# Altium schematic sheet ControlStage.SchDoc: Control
size A3; Date: Not shown in title block; ApprovedBy: Not shown in title block; CheckedBy: Not shown in title block; Author: Not shown in title block; CompanyName: Not shown in title block; DrawnBy: Hely Zhang; Engineer: Hely Zhang; Organization: Not shown in title block; Address1: Not shown in title block; Address2: Not shown in title block; Address3: Not shown in title block; Address4: Not shown in title block; DocumentNumber: 5; Revision: Use project parameter SCH_Rev; SheetNumber: 5; SheetTotal: 6; PageSetup: Record=PageOptions¦CenterHorizontal=True¦CenterVertical=True¦PrintScale=1.00¦XCorrection=1.00¦YCorrection=1.00¦PrintKind=0¦BorderSize=5000000¦LeftOffset=0¦BottomOffset=0¦Orientation=2¦PaperLength=1000¦PaperWidth=1000¦Scale=100¦PaperSource=15¦PrintQuality=600¦MediaType=1¦DitherType=10¦PaperKind=Letter¦PrintScaleMode=1
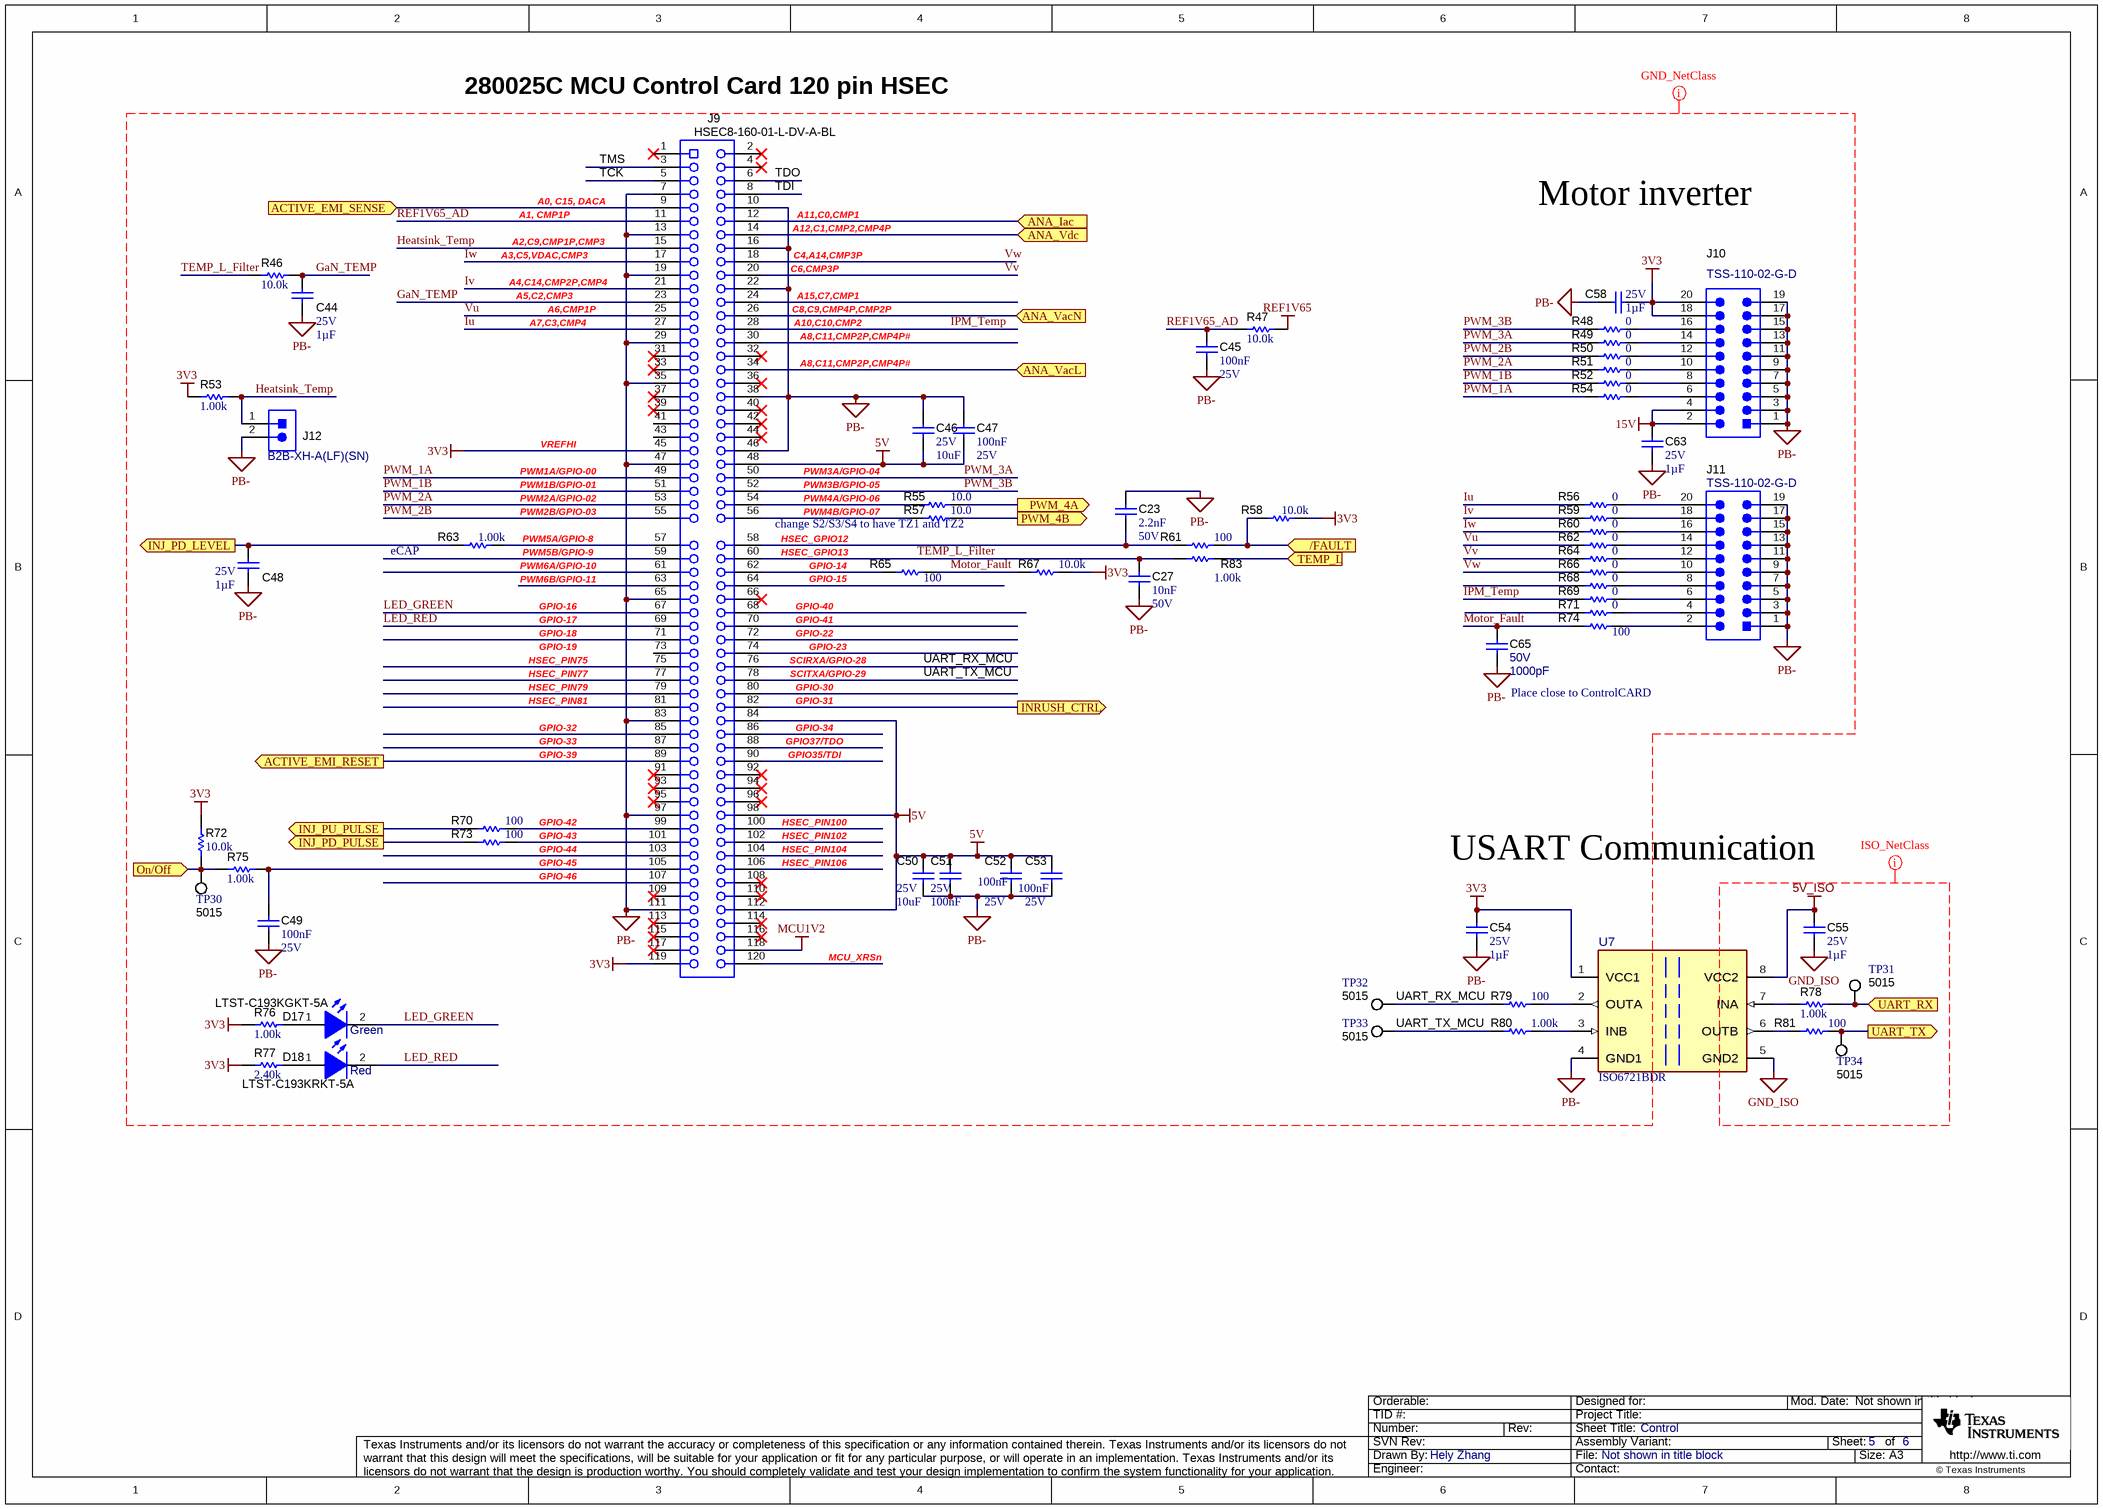
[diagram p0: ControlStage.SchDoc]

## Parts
C23  Cap_F: 2.2nF  VDC_V: 50V  [0603]  (hidden comment: GRM188R71H222KA01D)
C27  Cap_F: 10nF  VDC_V: 50V  [0603]  (hidden comment: GRM188R71H103KA01D)
C44  VDC_V: 25V  Cap_F: 1µF  [0603]  (hidden comment: GRJ188R71E105KE11D)
C45  Cap_F: 100nF  VDC_V: 25V  [0603]  (hidden comment: GRM188R71E104KA01D)
C46  VDC_V: 25V  ValueDisplayed: 10uF  [1206_180]  (hidden comment: GRM31CR71E106KA12L)
C47  Cap_F: 100nF  VDC_V: 25V  [0603]  (hidden comment: GRM188R71E104KA01D)
C48  VDC_V: 25V  Cap_F: 1µF  [0603]  (hidden comment: GRJ188R71E105KE11D)
C49  Cap_F: 100nF  VDC_V: 25V  [0603]  (hidden comment: GRM188R71E104KA01D)
C50  VDC_V: 25V  ValueDisplayed: 10uF  [1206_180]  (hidden comment: GRM31CR71E106KA12L)
C51  Cap_F: 100nF  VDC_V: 25V  [0603]  (hidden comment: GRM188R71E104KA01D)
C52  Cap_F: 100nF  VDC_V: 25V  [0603]  (hidden comment: GRM188R71E104KA01D)
C53  Cap_F: 100nF  VDC_V: 25V  [0603]  (hidden comment: GRM188R71E104KA01D)
C54  VDC_V: 25V  Cap_F: 1µF  [0603]  (hidden comment: GRJ188R71E105KE11D)
C55  VDC_V: 25V  Cap_F: 1µF  [0603]  (hidden comment: GRJ188R71E105KE11D)
C58  VDC_V: 25V  Cap_F: 1µF  [0603]  (hidden comment: GRJ188R71E105KE11D)
C63  VDC_V: 25V  Cap_F: 1µF  [0603]  (hidden comment: GRJ188R71E105KE11D)
C65  VDC_V: 50V  ValueDisplayed: 1000pF  [0603]  (hidden comment: GCJ188R71H102KA01D)
D17  LTST-C193KGKT-5A  value Green  [LTST-C193_Green]
D18  LTST-C193KRKT-5A  value Red  [LTST-C193_Red]
J9  HSEC8-160-01-L-DV-A-BL  [controlCARD-120HSEC]
J10  TSS-110-02-G-D  [Samtec_TSS-110-02-G-D]
J11  TSS-110-02-G-D  [Samtec_TSS-110-02-G-D]
J12  B2B-XH-A(LF)(SN)  [JST_B2B-XH-A]
R46  ValueDisplayed: 10.0k  [0603]  (hidden comment: RC0603FR-0710KL)
R47  ValueDisplayed: 10.0k  [0603]  (hidden comment: RC0603FR-0710KL)
R48  ValueDisplayed: 0  [0603]  (hidden comment: RC0603JR-070RL)
R49  ValueDisplayed: 0  [0603]  (hidden comment: RC0603JR-070RL)
R50  ValueDisplayed: 0  [0603]  (hidden comment: RC0603JR-070RL)
R51  ValueDisplayed: 0  [0603]  (hidden comment: RC0603JR-070RL)
R52  ValueDisplayed: 0  [0603]  (hidden comment: RC0603JR-070RL)
R53  ValueDisplayed: 1.00k  [0603]  (hidden comment: RC0603FR-071KL)
R54  ValueDisplayed: 0  [0603]  (hidden comment: RC0603JR-070RL)
R55  ValueDisplayed: 10.0  [0603]  (hidden comment: RC0603FR-0710RL)
R56  ValueDisplayed: 0  [0603]  (hidden comment: RC0603JR-070RL)
R57  ValueDisplayed: 10.0  [0603]  (hidden comment: RC0603FR-0710RL)
R58  ValueDisplayed: 10.0k  [0603]  (hidden comment: RC0603FR-0710KL)
R59  ValueDisplayed: 0  [0603]  (hidden comment: RC0603JR-070RL)
R60  ValueDisplayed: 0  [0603]  (hidden comment: RC0603JR-070RL)
R61  ValueDisplayed: 100  [0603]  (hidden comment: RC0603FR-07100RL)
R62  ValueDisplayed: 0  [0603]  (hidden comment: RC0603JR-070RL)
R63  ValueDisplayed: 1.00k  [0603]  (hidden comment: RC0603FR-071KL)
R64  ValueDisplayed: 0  [0603]  (hidden comment: RC0603JR-070RL)
R65  ValueDisplayed: 100  [0603]  (hidden comment: RC0603FR-07100RL)
R66  ValueDisplayed: 0  [0603]  (hidden comment: RC0603JR-070RL)
R67  ValueDisplayed: 10.0k  [0603]  (hidden comment: RC0603FR-0710KL)
R68  ValueDisplayed: 0  [0603]  (hidden comment: RC0603JR-070RL)
R69  ValueDisplayed: 0  [0603]  (hidden comment: RC0603JR-070RL)
R70  ValueDisplayed: 100  [0603]  (hidden comment: RC0603FR-07100RL)
R71  ValueDisplayed: 0  [0603]  (hidden comment: RC0603JR-070RL)
R72  ValueDisplayed: 10.0k  [0603]  (hidden comment: RC0603FR-0710KL)
R73  ValueDisplayed: 100  [0603]  (hidden comment: RC0603FR-07100RL)
R74  ValueDisplayed: 100  [0603]  (hidden comment: RC0603FR-07100RL)
R75  ValueDisplayed: 1.00k  [0603]  (hidden comment: RC0603FR-071KL)
R76  ValueDisplayed: 1.00k  [0603]  (hidden comment: RC0603FR-071KL)
R77  ValueDisplayed: 2.40k  [0603]  (hidden comment: RC0603FR-072K4L)
R78  ValueDisplayed: 1.00k  [0603]  (hidden comment: RC0603FR-071KL)
R79  ValueDisplayed: 100  [0603]  (hidden comment: RC0603FR-07100RL)
R80  ValueDisplayed: 1.00k  [0603]  (hidden comment: RC0603FR-071KL)
R81  ValueDisplayed: 100  [0603]  (hidden comment: RC0603FR-07100RL)
R83  ValueDisplayed: 1.00k  [0603]  (hidden comment: RC0603FR-071KL)
TP30  5015  [Testpoint_Keystone_Miniature]
TP31  5015  [Testpoint_Keystone_Miniature]
TP32  5015  [Testpoint_Keystone_Miniature]
TP33  5015  [Testpoint_Keystone_Miniature]
TP34  5015  [Testpoint_Keystone_Miniature]
U7  ISO6721BDR  [D0008A-MFG]

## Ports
/FAULT (in), ACTIVE_EMI_RESET (out), ACTIVE_EMI_SENSE (in), ANA_Iac (in), ANA_VacL (in), ANA_VacN (in), ANA_Vdc (in), INJ_PD_LEVEL (out), INJ_PD_PULSE (out), INJ_PU_PULSE (out), INRUSH_CTRL (out), On/Off (in), PWM_4A (out), PWM_4B (out), TEMP_L (in), UART_RX (in), UART_TX (out)

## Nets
3V3: C54.1 C58.1 J9.45 J9.119 J10.18 J10.20 R53.2 R58.2 R67.2 R72.2 R76.2 R77.2 U7.1(VCC1)
5V: C46.2 C47.2 C50.1 C51.1 C52.1 C53.1 J9.48 J9.84 J9.98 J9.112
5V_ISO: C55.1 U7.8(VCC2)
15V: C63.1 J10.2 J10.4
GND_ISO: C55.2 U7.5(GND2)
MCU1V2: J9.118
PB-: C23.1 C27.2 C44.2 C45.2 C46.1 C47.1 C48.2 C49.2 C50.2 C51.2 C52.2 C53.2 C54.2 C58.2 C63.2 C65.1 J9.7 J9.10 J9.13 J9.16 J9.19 J9.22 J9.29 J9.35 J9.38 J9.46 J9.47 J9.65 J9.83 J9.97 J9.111 J10.1 J10.3 J10.5 J10.7 J10.9 J10.11 J10.13 J10.15 J10.17 J10.19 J11.1 J11.3 J11.5 J11.7 J11.9 J11.11 J11.13 J11.15 J11.17 J11.19 J12.2 U7.4(GND1)
REF1V65: R47.2
/FAULT: R58.1 R61.2 ; port /FAULT
ACTIVE_EMI_RESET: J9.89 ; port ACTIVE_EMI_RESET
ACTIVE_EMI_SENSE: J9.9 ; port ACTIVE_EMI_SENSE
ANA_Iac: J9.12 ; port ANA_Iac
ANA_VacL: J9.34 ; port ANA_VacL
ANA_VacN: J9.26 ; port ANA_VacN
ANA_Vdc: J9.14 ; port ANA_Vdc
GaN_TEMP: C44.1 J9.23 R46.2
Heatsink_Temp: J9.15 J12.1 R53.1
INJ_PD_LEVEL: C48.1 R63.2 ; port INJ_PD_LEVEL
INJ_PD_PULSE: R73.1 ; port INJ_PD_PULSE
INJ_PU_PULSE: R70.1 ; port INJ_PU_PULSE
INRUSH_CTRL: J9.82 ; port INRUSH_CTRL
IPM_Temp: J9.28 R69.1
Iu: J9.27 R56.1
Iv: J9.21 R59.1
Iw: J9.17 R60.1
LED_GREEN: D17.2(K) J9.67
LED_RED: D18.2(K) J9.69
Motor_Fault: C65.2 R65.2 R67.1 R74.1
On/Off: R72.1 R75.2 TP30.1 ; port On/Off
PWM_1A: J9.49 R54.1
PWM_1B: J9.51 R52.1
PWM_2A: J9.53 R51.1
PWM_2B: J9.55 R50.1
PWM_3A: J9.50 R49.1
PWM_3B: J9.52 R48.1
PWM_4A: R55.2 ; port PWM_4A
PWM_4B: R57.2 ; port PWM_4B
REF1V65_AD: C45.1 J9.11 R47.1
TCK: J9.5
TDI: J9.8
TDO: J9.6
TEMP_L: R83.1 ; port TEMP_L
TEMP_L_Filter: C27.1 J9.60 R46.1 R83.2
TMS: J9.3
UART_RX: R78.1 TP31.1 ; port UART_RX
UART_RX_MCU: J9.76 R79.1 TP32.1
UART_TX: R81.2 TP34.1 ; port UART_TX
UART_TX_MCU: J9.78 R80.2 TP33.1
Vu: J9.25 R62.1
Vv: J9.20 R64.1
Vw: J9.18 R66.1
NetC23_2: C23.2 J9.58 R61.1
NetC49_1: C49.1 J9.105 R75.1
NetD17_1: D17.1(A) R76.1
NetD18_1: D18.1(A) R77.1
NetJ9_54: J9.54 R55.1
NetJ9_56: J9.56 R57.1
NetJ9_57: J9.57 R63.1
NetJ9_62: J9.62 R65.1
NetJ9_99: J9.99 R70.2
NetJ9_101: J9.101 R73.2
NetJ10_6: J10.6 R54.2
NetJ10_8: J10.8 R52.2
NetJ10_10: J10.10 R51.2
NetJ10_12: J10.12 R50.2
NetJ10_14: J10.14 R49.2
NetJ10_16: J10.16 R48.2
NetJ11_2: J11.2 R74.2
NetJ11_4: J11.4 R71.2
NetJ11_6: J11.6 R69.2
NetJ11_8: J11.8 R68.2
NetJ11_10: J11.10 R66.2
NetJ11_12: J11.12 R64.2
NetJ11_14: J11.14 R62.2
NetJ11_16: J11.16 R60.2
NetJ11_18: J11.18 R59.2
NetJ11_20: J11.20 R56.2
NetR78_2: R78.2 U7.7(INA)
NetR79_2: R79.2 U7.2(OUTA)
NetR80_1: R80.1 U7.3(INB)
NetR81_1: R81.1 U7.6(OUTB)

Not connected (* = marked no-connect by the designer): J9 1* 2* 4* 24 30 31* 32* 33* 36* 37* 39* 40* 41 42* 43 44* 59 61 63 64 66* 68 70 71 72 73 74 75 77 79 80 81 85 86 87 88 90 91* 92* 93* 94* 95* 96* 100 102 103 104 106 107 108* 109* 110* 113* 114* 115* 116* 117* 120; R68 1; R71 1

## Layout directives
net class GND_NetClass: 3V3, 5V, 5V_ISO, 15V, GaN_TEMP, GND_ISO, Heatsink_Temp, IPM_Temp, Iu, Iv, Iw, LED_GREEN, LED_RED, MCU1V2, Motor_Fault, PB-, PWM_1A, PWM_1B, PWM_2A, PWM_2B, PWM_3A, PWM_3B, REF1V65, REF1V65_AD, TCK, TDI, TDO, TEMP_L_Filter, TMS, UART_RX_MCU, UART_TX_MCU, Vu, Vv, Vw
net class ISO_NetClass: 5V_ISO, GND_ISO

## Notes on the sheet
- 280025C MCU Control Card 120 pin HSEC
- A1, CMP1P
- A3,C5,VDAC,CMP3
- A2,C9,CMP1P,CMP3
- A0, C15, DACA
- A11,C0,CMP1
- C4,A14,CMP3P
- A12,C1,CMP2,CMP4P
- Motor inverter
- A5,C2,CMP3
- A4,C14,CMP2P,CMP4
- A7,C3,CMP4
- A6,CMP1P
- C6,CMP3P
- A15,C7,CMP1
- A10,C10,CMP2
- C8,C9,CMP4P,CMP2P
- A8,C11,CMP2P,CMP4P#
- VREFHI
- PWM1A/GPIO-00
- PWM1B/GPIO-01
- PWM2A/GPIO-02
- (near R63) PWM2B/GPIO-03
- PWM3A/GPIO-04
- PWM3B/GPIO-05
- PWM4A/GPIO-06
- PWM4B/GPIO-07
- (near R63) eCAP
- (near R63) PWM5A/GPIO-8
- (near R63) PWM5B/GPIO-9
- (near R63) PWM6A/GPIO-10
- (near R63) PWM6B/GPIO-11
- (near R57) change S2/S3/S4 to have TZ1 and TZ2
- HSEC_GPIO12
- HSEC_GPIO13
- GPIO-14
- GPIO-15
- GPIO-16
- GPIO-17
- GPIO-18
- GPIO-19
- HSEC_PIN75
- GPIO-40
- GPIO-41
- GPIO-22
- GPIO-23
- SCIRXA/GPIO-28
- HSEC_PIN77
- HSEC_PIN79
- HSEC_PIN81
- GPIO-32
- GPIO-30
- GPIO-31
- GPIO-34
- SCITXA/GPIO-29
- (near C65) Place close to ControlCARD
- GPIO-33
- GPIO-39
- GPIO37/TDO
- GPIO35/TDI
- GPIO-42
- GPIO-43
- GPIO-44
- GPIO-45
- HSEC_PIN100
- HSEC_PIN102
- HSEC_PIN104
- HSEC_PIN106
- GPIO-46
- USART Communication
- MCU_XRSn

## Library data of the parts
C23 = CMP-0007443-4: CAP, CERM, 2200 pF, 50 V, +/- 10%, X7R, 0603; Manufacturer: MuRata; TaMin_C: -55°C; Polarized: N; SizeAreaWB_mm2: 4.68; Value1: Unknown; U/M: EA; Value: 2200pF; TaMax_C: 125°C; SizeZ_mm: 1; SizeX_mm: 1.6; SizeY_mm: 0.8; SizeArea_mm2: 1.28; AEC Category: Q200
C27 = CMP-0007433-4: CAP, CERM, 0.01 uF, 50 V, +/- 10%, X7R, 0603; Manufacturer: MuRata; TaMin_C: -55°C; Polarized: N; SizeAreaWB_mm2: 4.68; Value1: Unknown; U/M: EA; Value: 0.01uF; TaMax_C: 125°C; SizeZ_mm: 1; SizeX_mm: 1.6; SizeY_mm: 0.8; SizeArea_mm2: 1.28; AEC Category: Q200
C44 C48 C54 C55 C58 C63 = CMP-0079720-2: CAP, CERM, 1 µF, 25 V,+/- 10%, X7R, 0603; Manufacturer: MuRata; AEC Category: Q200; TaMin_C: -55°C; AEC Qualified: N; SizeAreaWB_mm2: 4.68; SizeArea_mm2: 1.28; Value: 1uF; SizeZ_mm: 1; SizeX_mm: 1.6; U/M: EA; MFG_Status: TI_Obsolete; SizeY_mm: 0.8; TaMax_C: 125°C
C45 C47 C49 C51-C53 = CMP-0007404-5: CAP, CERM, 0.1 uF, 25 V, +/- 10%, X7R, 0603; Manufacturer: MuRata; ValueDisplayed: 0.1uF; SizeAreaWB_mm2: 4.68; MFG_Status: TI_Obsolete; SizeZ_mm: 1; SizeY_mm: 0.8; Value: 0.1uF; AEC Category: Q200; Value1: Unknown; SizeX_mm: 1.6; TaMin_C: -55°C; Polarized: N; TaMax_C: 125°C; SizeArea_mm2: 1.28; U/M: EA
C46 C50 = CMP-0008965-2: CAP, CERM, 10 uF, 25 V, +/- 10%, X7R, 1206; Manufacturer: MuRata; TaMin_C: -55°C; Polarized: N; SizeAreaWB_mm2: 10.92; Value1: Unknown; U/M: EA; Value: 10uF; TaMax_C: 125°C; SizeZ_mm: 1.8; SizeX_mm: 3.2; SizeY_mm: 1.6; Cap_Case: 2220; SizeArea_mm2: 5.12; Cap_F: 10µF; AEC Category: Q200
C65 = CMP-0007432-5: CAP, CERM, 1000 pF, 50 V, +/- 10%, X7R, 0603; Manufacturer: MuRata; TaMin_C: -55°C; Polarized: N; SizeAreaWB_mm2: 4.68; Value1: Unknown; U/M: EA; Value: 1000pF; TaMax_C: 125°C; SizeZ_mm: 1; SizeX_mm: 1.6; SizeY_mm: 0.8; SizeArea_mm2: 1.28; Cap_F: 1nF; AEC Category: Q200
D17 = CMP-0079921-3: LED, Green, SMD; Manufacturer: Lite-On; Tjmax_C: 85°C; Value2: 2V; SizeY_mm: 0.8; Io_A: 5mA; SizeAreaWB_mm2: 4.68; Type: AlInGaP; SizeX_mm: 1.6; SizeZ_mm: 0.45; SizeArea_mm2: 1.28; Value1: W
D18 = CMP-0079922-3: LED, Red, SMD; Manufacturer: Lite-On; SizeX_mm: 1.6; Value2: 2V; SizeY_mm: 0.8; Green_REACh: Incomplete; SizeAreaWB_mm2: 4.68; Green_Lifecycle: Not Set; Value1: W; Io_A: 5mA; Type: AlInGaP; SizeZ_mm: 0.45; Tjmax_C: 85°C; SizeArea_mm2: 1.28
J9 = controlCARD-120HSEC: C2000 controlCARD-120HSEC connector, SMT; Manufacturer: Samtec; SymbolCreator: a0412235; Note: The pin numbering does not match Samtec datasheet
J10 J11 = CMP-0086128-1: Header(shrouded), 2.54mm, 10x2, Gold, TH; PartNumber: 612020235121; Manufacturer: Wurth; Gender: Male; Cert_UL: Y; Pitch_mm: 2.54; Voltage_V: 1kV; Current_A: 3A; Row_Count: 2
J12 = CMP-0075223-1: Header (Shrouded), 2.5mm, 2x1, Tin, TH; Manufacturer: JST Manufacturing; CNHeader: False; Current_A: 3A; Shrouded: Y; Gender: Male; Voltage_V: 250V; Row_Count: 1; Pitch_mm: 2.5
R46 R47 R58 R67 R72 = CMP-0022746-5: RES, 10.0 k, 1%, 0.1 W, 0603; Manufacturer: Yageo; Power_W: 100mW; TempCo: 100 ppm/C; Value_Code: 10k0; Value: 10.0k; EIA_Code: E96; Res_ohm: 10k; SizeX_mm: 1.6; SizeY_mm: 0.8; SizeZ_mm: 1; Value2: 0.1W; SizeArea_mm2: 1.28; AEC Qualified: N; VDC_V: 75V; AEC Category: Q200; SizeAreaWB_mm2: 4.68
R48-R52 R54 R56 R59 R60 R62 R64 R66 R68 R69 R71 = CMP-0025885-5: RES, 0, 5%, 0.1 W, 0603; Manufacturer: Yageo; Power_W: 100mW; TempCo: 200 ppm/C; Value_Code: 0000; Value: 0; EIA_Code: E24; SizeX_mm: 1.6; SizeZ_mm: 1; Value2: 0.1W; SizeArea_mm2: 1.28; AEC Qualified: N; VDC_V: 75V; AEC Category: Q200; SizeY_mm: 0.8; SizeAreaWB_mm2: 4.68
R53 R63 R75 R76 R78 R80 R83 = CMP-0022895-5: RES, 1.00 k, 1%, 0.1 W, 0603; Manufacturer: Yageo; Power_W: 100mW; TempCo: 100 ppm/C; Value_Code: 1k00; Value: 1.00k; EIA_Code: E96; Res_ohm: 1k; SizeX_mm: 1.6; SizeY_mm: 0.8; SizeZ_mm: 1; Value2: 0.1W; SizeArea_mm2: 1.28; AEC Qualified: N; VDC_V: 75V; AEC Category: Q200; SizeAreaWB_mm2: 4.68
R55 R57 = CMP-0022751-4: RES, 10.0, 1%, 0.1 W, 0603; Manufacturer: Yageo; Power_W: 100mW; TempCo: 100 ppm/C; Value_Code: 10R0; Value: 10.0; EIA_Code: E96; Res_ohm: 10; SizeX_mm: 1.6; SizeY_mm: 0.8; SizeZ_mm: 1; Value2: 0.1W; SizeArea_mm2: 1.28; AEC Qualified: N; VDC_V: 75V; AEC Category: Q200; SizeAreaWB_mm2: 4.68
R61 R65 R70 R73 R74 R79 R81 = CMP-0022736-4: RES, 100, 1%, 0.1 W, 0603; Manufacturer: Yageo; Power_W: 100mW; TempCo: 100 ppm/C; Value_Code: 100R; Value: 100; EIA_Code: E96; SizeX_mm: 1.6; SizeY_mm: 0.8; SizeZ_mm: 1; Value2: 0.1W; SizeArea_mm2: 1.28; AEC Qualified: N; VDC_V: 75V; AEC Category: Q200; SizeAreaWB_mm2: 4.68
R77 = CMP-0022991-5: RES, 2.40 k, 1%, 0.1 W, 0603; Manufacturer: Yageo; Power_W: 100mW; TempCo: 100 ppm/C; Value_Code: 2k40; Value: 2.40k; Res_ohm: 2.4k; SizeX_mm: 1.6; SizeY_mm: 0.8; SizeZ_mm: 1; Value2: 0.1W; SizeArea_mm2: 1.28; AEC Qualified: N; VDC_V: 75V; AEC Category: Q200; SizeAreaWB_mm2: 4.68
TP30-TP34 = CMP-0055152-1: Test Point, Miniature, SMT; Manufacturer: Keystone; CNHeader: FALSE; Green_Lifecycle: Active; Green_REACh: Passed; CT: TRUE
U7 = CMP-0089949-1: Low Speed, General Purpose, Robust EMC, Dual-Channel Digital Isolators; Manufacturer: Texas Instruments; TJmax_C: +150°C; TaMin_C: -40°C; SizeZ_mm: 1.75mm; Min Supply Voltage: 1.71V; Standoff Height: 0.11mm; AEC Qualified: Yes; TaMax_C: +125°C; AEC Grade: Grade 1; Max Supply Voltage: 5.5V; Interface: LVCMOS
